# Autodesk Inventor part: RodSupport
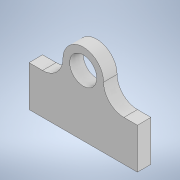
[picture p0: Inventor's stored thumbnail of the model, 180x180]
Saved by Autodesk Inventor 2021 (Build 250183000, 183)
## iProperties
Created: 2026-10
Part Number: RodSupport
Material: Generic
Document SubType Name: Modeling
Designer: hp
Density: 1 g/cm^3
Appearance: Default
Author: hp
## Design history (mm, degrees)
sketch "Sketch2"
  geometry: L1 (-20, 15)-(20, 15); L2 (20, 15)-(20, 0); L3 (20, 0)-(-20, 0); L4 (-20, 0)-(-20, 15); C1 r 5 at (0, 22.5); A1 r 7.5 centre (-15, 22.5) between (-15, 15) and (-7.5, 22.5); A2 r 7.5 centre (0, 22.5) between (7.5, 22.5) and (-7.5, 22.5); A3 r 7.5 centre (15, 22.5) between (7.5, 22.5) and (15, 15); 2 further points
  constraints: 8 end point, 6 point on circle, 5 tangent, 4 centre point, 2 midpoint, 2 parallel, 2 point on line, 1 coincident, 1 concentric, 1 horizontal, 1 perpendicular, 1 vertical alignment
  dimensions: "d1" = 40 distance of L2.end L3.end; "d2" = 15 distance of L1.end L2.end; "d5" = 15 diameter of A1; "d6" = 15 diameter of A2; "d7" = 15 diameter of A3; "d8" = 10 diameter of C1
extrude "Extrusion1" new body sketch "Sketch2" distance "d9" = 5; taper "d10" = 0 deg
body "Solid1"
